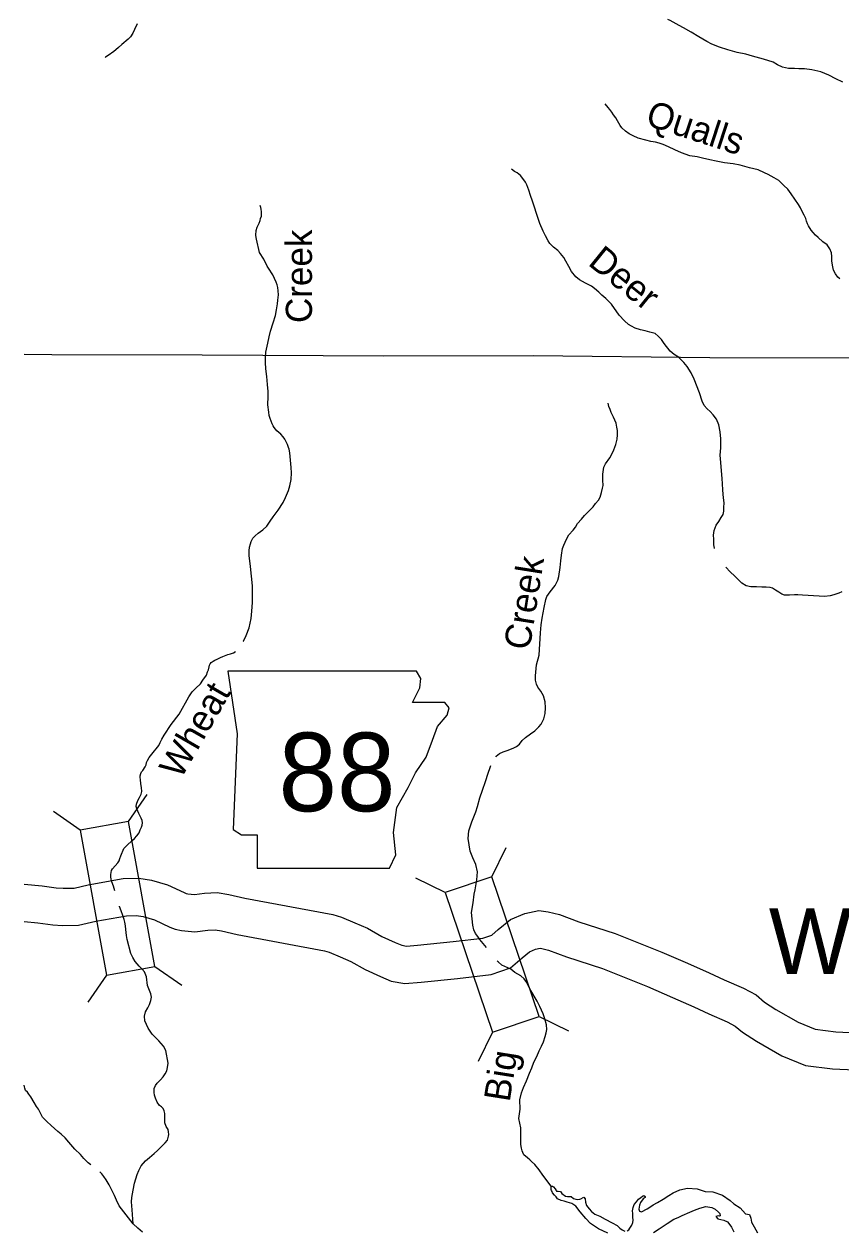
# Model space of a CAD drawing. Extents: x -492261 to -432772, y 1441225 to 1452922.
# Drawn here: x -461914.6 to -461749.9, y 1452450.6 to 1452693.5 of the extents above; entities that cross this region are included whole.
import ezdxf

# ---------------------------------------------------------------- set-up
doc = ezdxf.new("R2010")
doc.units = 0
doc.layers.add('Default', color=7, linetype='Continuous')

msp = doc.modelspace()

# ---------------------------------------------------------------- linework, layer by layer
at = {"layer": 'Default'}
for p, q in [((-461893.49, 1452532.85), (-461889.73, 1452538.27)), ((-461903.23, 1452531.08), (-461908.65, 1452534.84)), ((-461820.3, 1452521.7), (-461817.38, 1452527.62)), ((-461829.68, 1452518.52), (-461835.6, 1452521.43)), ((-461888.19, 1452503.63), (-461882.77, 1452499.87)), ((-461897.93, 1452501.86), (-461901.69, 1452496.44)), ((-461810.75, 1452493.58), (-461804.83, 1452490.66)), ((-461820.13, 1452490.39), (-461823.05, 1452484.47))]:
    msp.add_line(p, q, dxfattribs=at)
for points in [[(-461891.79, 1452693.56), (-461892.3, 1452692.45), (-461892.67, 1452691.72), (-461893.11, 1452690.94), (-461893.55, 1452690.51), (-461894.89, 1452689.39), (-461895.53, 1452688.83), (-461896.1, 1452688.38), (-461896.5, 1452688.02), (-461897.61, 1452687.23), (-461898.13, 1452686.88), (-461898.2, 1452686.8)], [(-461772.69, 1452688.32), (-461774.36, 1452688.88), (-461775.92, 1452689.49), (-461776.97, 1452690), (-461778.58, 1452690.94), (-461780.11, 1452691.89), (-461781.62, 1452692.75), (-461782.52, 1452693.24), (-461783.72, 1452693.91), (-461784.3, 1452694.25), (-461784.83, 1452694.47)], [(-461749.54, 1452681.8), (-461750.94, 1452682.51), (-461752.32, 1452683.25), (-461753.98, 1452683.93), (-461755.8, 1452684.31), (-461757.23, 1452684.5), (-461758.37, 1452684.53), (-461759.27, 1452684.57), (-461760, 1452684.56), (-461760.45, 1452684.58), (-461761.67, 1452684.85), (-461762.7, 1452685.33), (-461763.6, 1452685.87), (-461765.51, 1452686.48), (-461767.73, 1452687.08), (-461769.08, 1452687.49), (-461770.83, 1452687.84), (-461772.69, 1452688.32)], [(-461750.13, 1452642.19), (-461750.55, 1452642.55), (-461751.03, 1452643.22), (-461751.39, 1452643.94), (-461751.57, 1452644.64), (-461751.73, 1452645.76), (-461751.72, 1452646.71), (-461751.82, 1452647.44), (-461752.13, 1452648.26), (-461752.71, 1452649.03), (-461753.54, 1452649.67), (-461754.5, 1452650.51), (-461755.03, 1452651.03), (-461755.54, 1452651.55), (-461755.94, 1452652.02), (-461756.45, 1452652.87), (-461756.68, 1452653.29), (-461756.88, 1452653.81), (-461757.01, 1452654.36), (-461757.32, 1452655.01), (-461757.75, 1452655.76), (-461758.08, 1452656.5), (-461758.46, 1452657.17), (-461759.17, 1452658.24), (-461759.91, 1452659.36), (-461760.64, 1452660.25), (-461761.45, 1452661.02), (-461762.43, 1452662.03), (-461763.34, 1452662.57), (-461764.59, 1452663.21), (-461765.32, 1452663.55), (-461766.62, 1452664.14), (-461768.32, 1452664.57), (-461770.2, 1452665.08), (-461771.62, 1452665.36), (-461773.37, 1452665.61), (-461775.05, 1452665.92), (-461776.35, 1452666.16), (-461777.8, 1452666.54), (-461778.9, 1452666.78), (-461780.4, 1452667.01), (-461782.03, 1452667.57), (-461783.36, 1452668.2), (-461784.66, 1452668.77), (-461785.71, 1452669.28), (-461786.54, 1452669.57), (-461787.31, 1452669.76), (-461788.21, 1452669.9), (-461789.24, 1452670.12), (-461790.77, 1452670.57), (-461791.79, 1452670.99), (-461792.57, 1452671.4), (-461793.35, 1452671.95), (-461794.06, 1452672.61), (-461794.44, 1452673.13), (-461794.67, 1452673.58), (-461794.94, 1452674.06), (-461795.3, 1452674.63), (-461795.73, 1452675.25), (-461796.11, 1452675.79), (-461796.47, 1452676.34), (-461796.82, 1452676.76), (-461797.4, 1452677.48)], [(-461775.37, 1452587.84), (-461775.41, 1452587.92), (-461775.54, 1452588.57), (-461775.55, 1452589.75), (-461775.59, 1452590.58), (-461775.49, 1452591.48), (-461775.06, 1452592.53), (-461774.54, 1452593.27), (-461774.03, 1452594.12), (-461773.68, 1452594.7), (-461773.54, 1452595.38), (-461773.52, 1452596.13), (-461773.48, 1452597.06), (-461773.59, 1452598.06), (-461773.71, 1452599.63), (-461773.77, 1452600.98), (-461773.88, 1452601.91), (-461774.14, 1452605.16), (-461774.23, 1452606.69), (-461774.15, 1452608.16), (-461774.12, 1452609.94), (-461774.28, 1452611.39), (-461774.52, 1452612.76), (-461774.98, 1452613.89), (-461775.66, 1452614.8), (-461776.27, 1452615.45), (-461776.85, 1452615.99), (-461777.45, 1452616.71), (-461777.89, 1452617.58), (-461778.43, 1452619.23), (-461779.48, 1452621.99), (-461780.09, 1452623.26), (-461780.9, 1452624.51), (-461781.59, 1452625.35), (-461782.65, 1452626.41), (-461783.5, 1452626.95), (-461784.33, 1452627.65), (-461785.57, 1452629.16), (-461786.1, 1452629.95), (-461786.76, 1452630.65), (-461787.36, 1452631.17), (-461787.91, 1452631.31), (-461788.46, 1452631.48), (-461789.36, 1452631.72), (-461790.31, 1452631.93), (-461791.37, 1452632.27), (-461792.14, 1452632.69), (-461792.7, 1452633.03), (-461793.55, 1452633.72), (-461794.59, 1452634.91), (-461796.13, 1452637.1), (-461796.76, 1452637.72), (-461797.32, 1452638.24), (-461798.1, 1452638.93), (-461798.7, 1452639.5), (-461799.61, 1452640.24), (-461800.21, 1452640.73), (-461801.37, 1452641.32), (-461802.62, 1452642.03), (-461803.35, 1452642.62), (-461804.23, 1452643.69), (-461804.74, 1452644.71), (-461805.38, 1452645.75), (-461805.79, 1452646.52), (-461806.44, 1452647.34), (-461807, 1452647.91), (-461807.88, 1452648.6), (-461808.56, 1452649.3), (-461808.94, 1452649.89), (-461809.47, 1452650.86), (-461809.96, 1452651.83), (-461810.57, 1452653.38), (-461811.27, 1452655.35), (-461811.71, 1452656.67), (-461812.09, 1452657.84), (-461812.48, 1452658.99), (-461812.84, 1452660.09), (-461813.25, 1452661.16), (-461813.5, 1452661.68), (-461813.81, 1452662.15), (-461814.47, 1452663), (-461815.15, 1452663.56), (-461815.72, 1452663.86), (-461816.33, 1452664.28)], [(-461866.45, 1452591.6), (-461865.66, 1452592.38), (-461864.99, 1452593.37), (-461864.33, 1452594.27), (-461863.37, 1452595.61), (-461862.36, 1452597.1), (-461861.9, 1452598.13), (-461861.29, 1452599.54), (-461860.98, 1452600.49), (-461860.74, 1452601.77), (-461860.68, 1452603.13), (-461860.74, 1452604.2), (-461860.88, 1452605.63), (-461861.02, 1452607.13), (-461861.13, 1452607.9), (-461861.23, 1452608.2), (-461861.46, 1452608.82), (-461861.72, 1452609.37), (-461862, 1452609.89), (-461862.33, 1452610.39), (-461862.81, 1452610.89), (-461863.61, 1452611.58), (-461864.17, 1452612.22), (-461864.34, 1452612.57), (-461864.55, 1452612.99), (-461864.96, 1452614.07), (-461865.14, 1452614.69), (-461865.25, 1452615.31), (-461865.41, 1452616.84), (-461865.33, 1452618.47), (-461865.39, 1452619.52), (-461865.48, 1452620.94), (-461865.65, 1452622.49), (-461865.81, 1452624.04), (-461865.88, 1452625.32), (-461865.89, 1452626.39), (-461865.82, 1452627.4), (-461865.68, 1452628.02), (-461865.42, 1452629.23), (-461865.16, 1452630.53), (-461864.89, 1452631.64), (-461864.36, 1452633.35), (-461863.9, 1452634.83), (-461863.67, 1452635.98), (-461863.5, 1452637.16), (-461863.39, 1452637.91), (-461863.3, 1452638.99), (-461863.36, 1452639.81), (-461863.44, 1452640.44), (-461863.57, 1452640.99), (-461863.75, 1452641.54), (-461864.44, 1452643.01), (-461865.27, 1452644.32), (-461865.53, 1452644.77), (-461866.22, 1452646.14), (-461867.08, 1452647.48), (-461867.73, 1452650.18), (-461867.81, 1452650.53), (-461867.84, 1452651.03), (-461867.77, 1452651.95), (-461867.61, 1452652.58), (-461867.19, 1452653.44), (-461867, 1452653.96), (-461866.88, 1452654.37), (-461866.73, 1452654.84), (-461866.69, 1452655.19), (-461866.69, 1452655.67), (-461866.75, 1452656.22), (-461866.82, 1452656.57), (-461866.95, 1452656.97)], [(-461644.11, 1452625.59), (-461644.17, 1452625.59), (-461679.88, 1452625.65), (-461709.52, 1452625.91), (-461746.15, 1452626.19), (-461776.34, 1452626.27), (-461811.87, 1452626.66), (-461842.06, 1452626.62), (-461878.66, 1452626.85), (-461908.95, 1452626.91), (-461914.56, 1452626.93)], [(-461797.85, 1452600.54), (-461797.88, 1452601.61), (-461797.9, 1452602.86), (-461797.69, 1452604.22), (-461797.37, 1452604.95), (-461796.48, 1452606.16), (-461796.02, 1452607.01), (-461795.7, 1452607.77), (-461795.29, 1452608.8), (-461795.02, 1452609.88), (-461794.93, 1452610.76), (-461794.94, 1452611.66), (-461795.05, 1452612.31), (-461795.23, 1452613.1), (-461795.74, 1452614.35), (-461796.2, 1452615.25), (-461796.43, 1452615.84), (-461796.69, 1452616.49), (-461796.8, 1452617.12)], [(-461799.87, 1452596.26), (-461799.35, 1452596.93), (-461798.75, 1452597.59), (-461798.45, 1452598.22), (-461798.16, 1452599.15), (-461797.96, 1452600.02), (-461797.85, 1452600.54)], [(-461811.5, 1452562.21), (-461811.27, 1452564.44), (-461810.77, 1452566.37), (-461810.46, 1452570.88), (-461810.31, 1452572.51), (-461810.14, 1452573.79), (-461809.74, 1452575.95), (-461809.41, 1452577.6), (-461809.22, 1452578.2), (-461808.53, 1452579.14), (-461807.49, 1452580.43), (-461806.96, 1452581.51), (-461806.74, 1452582.24), (-461806.51, 1452584.02), (-461806.4, 1452585.4), (-461806.26, 1452586.55), (-461806, 1452587.88), (-461805.78, 1452588.56), (-461805.24, 1452589.74), (-461804.78, 1452590.64), (-461803.89, 1452591.53), (-461803.4, 1452592.19), (-461802.98, 1452592.87), (-461802.22, 1452593.8), (-461801.63, 1452594.54), (-461800.47, 1452595.65), (-461799.87, 1452596.26)], [(-461870.4, 1452569.13), (-461870.36, 1452569.2), (-461869.79, 1452570.31), (-461869.21, 1452571.89), (-461868.81, 1452573.75), (-461868.62, 1452575.23), (-461868.52, 1452576.96), (-461868.54, 1452578.96), (-461868.55, 1452580.36), (-461868.94, 1452584.23), (-461869.19, 1452586.46), (-461869.2, 1452587.41), (-461869.11, 1452588.16), (-461868.94, 1452588.77), (-461868.79, 1452589.24), (-461868.48, 1452589.95), (-461867.98, 1452590.43), (-461867.39, 1452590.96), (-461866.45, 1452591.6)], [(-461749.72, 1452579.11), (-461750.36, 1452578.87), (-461751.36, 1452578.51), (-461752.1, 1452578.3), (-461753.22, 1452578.21), (-461754.3, 1452578.23), (-461755.45, 1452578.29), (-461756.52, 1452578.38), (-461757.69, 1452578.46), (-461758.59, 1452578.53), (-461759.24, 1452578.55), (-461760.26, 1452578.48), (-461760.86, 1452578.43), (-461761.31, 1452578.47), (-461761.79, 1452578.64), (-461762.44, 1452579.04), (-461763.09, 1452579.48), (-461763.7, 1452579.85), (-461764.15, 1452579.99), (-461765, 1452580.06), (-461765.84, 1452580.1), (-461766.92, 1452580.11), (-461768.09, 1452580.15), (-461768.99, 1452580.34), (-461769.87, 1452580.85), (-461770.58, 1452581.52), (-461771.31, 1452582.26), (-461772.24, 1452583.13), (-461773.08, 1452584.07)], [(-461896.24, 1452518.89), (-461896.54, 1452519.8), (-461896.87, 1452520.69), (-461897, 1452521.22), (-461897.08, 1452521.67), (-461897.09, 1452522.14), (-461896.95, 1452522.94), (-461896.75, 1452523.3), (-461896.21, 1452523.9), (-461895.67, 1452524.49), (-461895.42, 1452524.89), (-461895.25, 1452525.39), (-461895.06, 1452525.94), (-461894.47, 1452527.4), (-461893.81, 1452528.11), (-461892.82, 1452528.97), (-461892.32, 1452529.4), (-461891.85, 1452529.94), (-461891.36, 1452530.59), (-461891.19, 1452531.14), (-461890.92, 1452531.7), (-461890.75, 1452532.13), (-461890.71, 1452532.58), (-461890.76, 1452533.08), (-461890.94, 1452533.5), (-461891.45, 1452534.47), (-461891.86, 1452535.42), (-461891.97, 1452535.87), (-461891.87, 1452536.32), (-461891.63, 1452537.05), (-461891.29, 1452537.7), (-461890.99, 1452538.33), (-461890.85, 1452538.86), (-461890.88, 1452539.68), (-461891.02, 1452540.43), (-461891.12, 1452541.28), (-461891.15, 1452541.73), (-461891.13, 1452542.06), (-461891.01, 1452542.51), (-461890.87, 1452542.84), (-461890.64, 1452543.14), (-461890.18, 1452543.87), (-461889.98, 1452544.27), (-461889.86, 1452544.73), (-461889.67, 1452545.15), (-461889.37, 1452545.73), (-461888.81, 1452546.44), (-461887.4, 1452548.16), (-461887.11, 1452548.76), (-461886.79, 1452549.42), (-461886.35, 1452550.22), (-461884.93, 1452552.42), (-461883.33, 1452554.49), (-461881.37, 1452557.94), (-461880.7, 1452558.97), (-461879.96, 1452559.71), (-461878.97, 1452560.57), (-461878.51, 1452561.35), (-461877.82, 1452562.36), (-461877.58, 1452562.99), (-461877.38, 1452563.44), (-461877.24, 1452564.02), (-461877.17, 1452564.32), (-461877.05, 1452564.64), (-461876.82, 1452564.87), (-461876.43, 1452565.18), (-461876.08, 1452565.33), (-461875.61, 1452565.56), (-461874.99, 1452565.87), (-461874.47, 1452566.13), (-461873.52, 1452566.49), (-461872.95, 1452566.62), (-461872.38, 1452566.83), (-461871.98, 1452567.06), (-461871.92, 1452567.14)], [(-461819.44, 1452545.89), (-461819.39, 1452545.98), (-461818.74, 1452546.53), (-461817.97, 1452546.87), (-461816.98, 1452547.25), (-461816.51, 1452547.44), (-461815.98, 1452547.64), (-461815.29, 1452547.97), (-461814.72, 1452548.46), (-461814.15, 1452549.16), (-461813.49, 1452549.75), (-461812.45, 1452550.49), (-461811.6, 1452551.1), (-461810.81, 1452551.91), (-461810.32, 1452552.49), (-461809.78, 1452553.52), (-461809.52, 1452554.6), (-461809.43, 1452555.75), (-461809.54, 1452556.93), (-461809.88, 1452558.15), (-461810.42, 1452559.14), (-461811, 1452559.94), (-461811.28, 1452560.49), (-461811.46, 1452561.33), (-461811.5, 1452562.21)], [(-461821.34, 1452507.43), (-461822.01, 1452508.23), (-461822.67, 1452509.05), (-461823.08, 1452509.69), (-461823.56, 1452510.31), (-461823.89, 1452511.03), (-461824.1, 1452511.93), (-461824.26, 1452513.21), (-461824.35, 1452514.48), (-461824.02, 1452516.49), (-461823.86, 1452518.19), (-461823.67, 1452519.1), (-461823.27, 1452521.1), (-461823.16, 1452522.73), (-461823.5, 1452524.18), (-461824.14, 1452525.55), (-461824.63, 1452526.84), (-461825.03, 1452529.42), (-461824.92, 1452530.97), (-461824.31, 1452532.75), (-461823.51, 1452534.82), (-461823.17, 1452535.87), (-461822.67, 1452537.63), (-461822.18, 1452539.14), (-461821.58, 1452540.92), (-461821, 1452542.58), (-461820.64, 1452543.76), (-461820.47, 1452544.14)], [(-461914.56, 1452520.24), (-461910.91, 1452519.87), (-461908.07, 1452519.48), (-461906.67, 1452519.42), (-461904.46, 1452519.44), (-461901.62, 1452520.09), (-461894.6, 1452521.37), (-461891.41, 1452521.4), (-461888.91, 1452521.01), (-461885.66, 1452520.06), (-461882.3, 1452518.51), (-461881.88, 1452518.35), (-461881.54, 1452518.27), (-461880.24, 1452518.14), (-461878.18, 1452518.4), (-461875.63, 1452518.53), (-461873.31, 1452518.17), (-461870.05, 1452517.4), (-461852.34, 1452514.08), (-461850.57, 1452513.6), (-461847.89, 1452512.46), (-461845.32, 1452511.33), (-461842.44, 1452509.69), (-461839.77, 1452508.49), (-461838.4, 1452507.93), (-461837.46, 1452507.75), (-461835.23, 1452507.95), (-461828.04, 1452508.67), (-461822.1, 1452509.37), (-461820.31, 1452509.97), (-461819.02, 1452511.1), (-461816.53, 1452513.13), (-461813.65, 1452514.29), (-461810.79, 1452514.89), (-461808.89, 1452514.63), (-461806.67, 1452514.14), (-461802.72, 1452512.63), (-461795.45, 1452510.29), (-461786, 1452506.51), (-461780.84, 1452504.28), (-461776.47, 1452502.33), (-461773.47, 1452500.94), (-461769.56, 1452499.25), (-461767.01, 1452497.89), (-461765.29, 1452496.46), (-461763.01, 1452494.98), (-461758.5, 1452492.38), (-461755.1, 1452490.99), (-461750.96, 1452490.47), (-461746.77, 1452490.29)], [(-461894.4, 1452513.09), (-461894.68, 1452513.91), (-461895.02, 1452514.86), (-461895.35, 1452515.75), (-461895.36, 1452515.77)], [(-461914.56, 1452512.7), (-461911.8, 1452512.42), (-461908.75, 1452512.01), (-461906.8, 1452511.92), (-461903.57, 1452511.95), (-461900.11, 1452512.75), (-461893.89, 1452513.87), (-461891.95, 1452513.89), (-461890.54, 1452513.67), (-461888.3, 1452513.02), (-461885.18, 1452511.57), (-461884.1, 1452511.17), (-461882.84, 1452510.86), (-461880.14, 1452510.59), (-461877.52, 1452510.92), (-461876.02, 1452511), (-461874.74, 1452510.8), (-461871.6, 1452510.06), (-461854.02, 1452506.77), (-461853.04, 1452506.5), (-461850.88, 1452505.58), (-461848.7, 1452504.62), (-461845.84, 1452503), (-461842.73, 1452501.6), (-461840.55, 1452500.7), (-461837.84, 1452500.18), (-461834.52, 1452500.48), (-461827.23, 1452501.21), (-461820.44, 1452502.01), (-461816.49, 1452503.35), (-461814.18, 1452505.37), (-461812.67, 1452506.6), (-461811.46, 1452507.09), (-461810.52, 1452507.29), (-461810.22, 1452507.25), (-461808.84, 1452506.94), (-461805.21, 1452505.55), (-461797.99, 1452503.23), (-461788.88, 1452499.59), (-461783.85, 1452497.41), (-461779.58, 1452495.51), (-461776.54, 1452494.1), (-461772.81, 1452492.48), (-461771.22, 1452491.63), (-461769.74, 1452490.41), (-461766.93, 1452488.58), (-461761.81, 1452485.63), (-461757.02, 1452483.67), (-461751.58, 1452482.98), (-461747.12, 1452482.8)], [(-461890.67, 1452450.08), (-461891.63, 1452450.87), (-461892.54, 1452451.76), (-461892.77, 1452454.59), (-461892.88, 1452456.21), (-461892.82, 1452457.11), (-461892.56, 1452458.54), (-461892.32, 1452459.97), (-461891.77, 1452461.68), (-461891.43, 1452462.49), (-461890.94, 1452463.49), (-461890.1, 1452464.45), (-461889.26, 1452465.16), (-461888.32, 1452465.97), (-461887.7, 1452466.58), (-461886.86, 1452467.37), (-461886.15, 1452468.08), (-461885.68, 1452468.63), (-461885.56, 1452468.93), (-461885.44, 1452469.41), (-461885.41, 1452469.76), (-461885.44, 1452470.31), (-461885.55, 1452470.76), (-461885.65, 1452470.99), (-461885.93, 1452471.38), (-461886.16, 1452472.13), (-461886.19, 1452472.76), (-461886.16, 1452474.03), (-461886.31, 1452474.53), (-461886.54, 1452474.98), (-461886.89, 1452475.35), (-461887.27, 1452475.65), (-461887.75, 1452476.32), (-461888.09, 1452477.09), (-461888.29, 1452477.71), (-461888.37, 1452478.21), (-461888.31, 1452479.04), (-461888.09, 1452479.64), (-461887.72, 1452480.15), (-461887.08, 1452480.76), (-461886.51, 1452481.39), (-461886.12, 1452481.97), (-461885.8, 1452482.62), (-461885.63, 1452483.3), (-461885.51, 1452484.13), (-461886.01, 1452486.7), (-461886.47, 1452487.57), (-461887.43, 1452488.66), (-461887.99, 1452489.28), (-461888.72, 1452490), (-461889.17, 1452490.62), (-461889.53, 1452491.22), (-461889.91, 1452491.91), (-461890.19, 1452492.71), (-461890.3, 1452493.59), (-461890.11, 1452494.46), (-461889.65, 1452495.27), (-461889.28, 1452496), (-461888.99, 1452496.75), (-461888.9, 1452497.43), (-461888.98, 1452498.13), (-461889.69, 1452499.8), (-461889.89, 1452501.52), (-461890.02, 1452501.87), (-461890.32, 1452502.52), (-461890.8, 1452503.14), (-461891.38, 1452503.68), (-461892.19, 1452504.65), (-461892.65, 1452505.45), (-461893.06, 1452506.24), (-461893.81, 1452509.09), (-461893.92, 1452509.89), (-461893.97, 1452510.46), (-461894.03, 1452511.06), (-461894.14, 1452511.81), (-461894.24, 1452512.56), (-461894.4, 1452513.09)], [(-461808.32, 1452459.34), (-461809.97, 1452461.56), (-461810.73, 1452462.68), (-461811.59, 1452463.74), (-461812.27, 1452464.36), (-461812.63, 1452464.68), (-461813.08, 1452465.08), (-461813.81, 1452465.67), (-461813.88, 1452465.82), (-461814.19, 1452466.47), (-461814.32, 1452467.01), (-461814.43, 1452467.76), (-461814.46, 1452468.36), (-461814.42, 1452469.69), (-461814.46, 1452471.14), (-461814.81, 1452472.99), (-461814.58, 1452474.9), (-461814.65, 1452476.77), (-461814.31, 1452478.15), (-461813.87, 1452479.23), (-461813.29, 1452480.59), (-461812.66, 1452482.1), (-461812.24, 1452483.23), (-461811.81, 1452484.36), (-461811.22, 1452485.5), (-461810.71, 1452486.65), (-461810.29, 1452487.56), (-461809.88, 1452488.44), (-461809.52, 1452489.52), (-461809.3, 1452490.25), (-461809.18, 1452490.95), (-461809.29, 1452491.9), (-461809.58, 1452493.05), (-461809.94, 1452494.1), (-461810.27, 1452494.82), (-461810.6, 1452495.54), (-461810.91, 1452496.26), (-461811.16, 1452496.66), (-461812.61, 1452499.15), (-461813.25, 1452500.39), (-461813.75, 1452501.14), (-461814.41, 1452501.73), (-461815.61, 1452502.44), (-461816.42, 1452503.11), (-461818.27, 1452503.89), (-461819.03, 1452504.56), (-461819.17, 1452504.72)], [(-461901.09, 1452463.67), (-461901.62, 1452464.07), (-461902.51, 1452464.94), (-461903.21, 1452465.71), (-461904.35, 1452466.84), (-461905.56, 1452468.26), (-461906.29, 1452469.1), (-461907.1, 1452469.84), (-461907.75, 1452470.41), (-461909.09, 1452471.57), (-461909.97, 1452472.39), (-461910.83, 1452473.28), (-461911.29, 1452474.2), (-461911.67, 1452474.87), (-461912.05, 1452475.44), (-461912.5, 1452476.21), (-461913.22, 1452477.38), (-461913.57, 1452477.9), (-461913.85, 1452478.28), (-461914.28, 1452478.65), (-461914.41, 1452479.14), (-461914.46, 1452479.37), (-461914.56, 1452479.69)], [(-461892.54, 1452451.76), (-461895.37, 1452455.38), (-461895.93, 1452456.53), (-461896.36, 1452457.47), (-461896.93, 1452458.67), (-461897.44, 1452459.64), (-461898.04, 1452460.66), (-461898.5, 1452461.33), (-461898.88, 1452461.85), (-461899.29, 1452462.28)], [(-461807.67, 1452457.53), (-461808.02, 1452457.99), (-461808.12, 1452458.29), (-461808.22, 1452458.51), (-461808.32, 1452458.66), (-461808.29, 1452458.84), (-461808.32, 1452459.34), (-461808.02, 1452459.34), (-461807.82, 1452459.21), (-461807.52, 1452458.81), (-461807.32, 1452458.49), (-461807.25, 1452458.34), (-461806.92, 1452458.34), (-461806.47, 1452458.26), (-461806.17, 1452457.88), (-461805.42, 1452457.38), (-461805, 1452457.31), (-461804.32, 1452457.26), (-461803.83, 1452456.91), (-461803.33, 1452456.73), (-461802.95, 1452456.68), (-461802.53, 1452456.71), (-461802.33, 1452456.81), (-461801.9, 1452457.11), (-461801.7, 1452457.16), (-461801.45, 1452456.81), (-461801.38, 1452456.16), (-461801.18, 1452455.48), (-461800.63, 1452454.81), (-461800.16, 1452454.25), (-461799.53, 1452453.73), (-461798.48, 1452453.35), (-461797.44, 1452452.7), (-461796.04, 1452451.95), (-461795.01, 1452451.45), (-461794.47, 1452450.92), (-461794.02, 1452450.57), (-461793.44, 1452450.3)], [(-461793.02, 1452450.37), (-461792.64, 1452450.57), (-461792.44, 1452450.87), (-461792.04, 1452451.52), (-461791.84, 1452452.05), (-461791.82, 1452452.53), (-461791.84, 1452453.13), (-461791.89, 1452453.88), (-461791.94, 1452454.38), (-461791.77, 1452455.03), (-461791.62, 1452455.65), (-461791.09, 1452456.23), (-461790.72, 1452456.75), (-461790.24, 1452457.05), (-461789.94, 1452457.33), (-461789.62, 1452457.48), (-461789.37, 1452457.3), (-461789.39, 1452457.1), (-461789.79, 1452456.8), (-461790.32, 1452456.05), (-461790.49, 1452455.55), (-461790.67, 1452454.73), (-461790.54, 1452454.33), (-461790.14, 1452454.18), (-461788.94, 1452454.78), (-461788.05, 1452455.38), (-461787.75, 1452455.58), (-461786.9, 1452456.08), (-461785.75, 1452456.75), (-461784.6, 1452457.45), (-461783.75, 1452458.03), (-461782.35, 1452458.65), (-461780.85, 1452458.98), (-461778.9, 1452458.83), (-461777.28, 1452458.3), (-461775.73, 1452458.23), (-461773.79, 1452457.53), (-461772.24, 1452456.5), (-461771.49, 1452455.82), (-461770.24, 1452454.97), (-461769.14, 1452453.8), (-461768.35, 1452453.67), (-461768.07, 1452452.92), (-461767.92, 1452452.12), (-461767.4, 1452451.14), (-461766.72, 1452449.94)], [(-461796.91, 1452449.9), (-461798.76, 1452450.75), (-461800.38, 1452451.85), (-461801.36, 1452452.83), (-461802.45, 1452454.18), (-461803.33, 1452455.33), (-461804.15, 1452455.86), (-461805.07, 1452456.13), (-461805.72, 1452456.33), (-461806.27, 1452456.46), (-461807.02, 1452456.83), (-461807.32, 1452457.18), (-461807.67, 1452457.53)], [(-461787.67, 1452450.02), (-461786.53, 1452450.75), (-461784.95, 1452451.85), (-461783.58, 1452452.7), (-461782.75, 1452453.05), (-461781.9, 1452453.45), (-461780.36, 1452454.12), (-461779.43, 1452454.5), (-461778.38, 1452454.92), (-461777.11, 1452455.27), (-461775.96, 1452455.05), (-461775.24, 1452454.72), (-461774.59, 1452454.15), (-461774.34, 1452453.85), (-461774.26, 1452453.37), (-461774.36, 1452453.32), (-461774.64, 1452453.37), (-461775.14, 1452453.27), (-461774.74, 1452452.77), (-461773.51, 1452452.5), (-461772.79, 1452452.15), (-461772.49, 1452451.87), (-461771.97, 1452451.09), (-461771.47, 1452450.17)]]:
    msp.add_lwpolyline(points, dxfattribs=at)
for points in [[(-461873.49, 1452563.17), (-461871.59, 1452550.48), (-461872.43, 1452531.23), (-461870.74, 1452530.18), (-461867.57, 1452530.18), (-461867.57, 1452523.41), (-461840.92, 1452523.41), (-461839.65, 1452526.16), (-461840.08, 1452530.6), (-461839.44, 1452535.67), (-461837.12, 1452539.69), (-461835.64, 1452542.65), (-461833.52, 1452545.82), (-461832.25, 1452549.21), (-461831.2, 1452551.96), (-461829.29, 1452554.28), (-461828.87, 1452555.76), (-461829.72, 1452556.82), (-461836.27, 1452556.82), (-461834.79, 1452559.78), (-461834.58, 1452561.69), (-461835.46, 1452563.15)], [(-461903.23, 1452531.08), (-461897.93, 1452501.86), (-461888.19, 1452503.63), (-461893.49, 1452532.85)], [(-461810.75, 1452493.58), (-461820.3, 1452521.7), (-461829.68, 1452518.52), (-461820.13, 1452490.39)]]:
    msp.add_lwpolyline(points, close=True, dxfattribs=at)

# ---------------------------------------------------------------- texts
for s, rotation, p in [('Qualls', 342, (-461789.53, 1452673.26)), ('Creek', 90, (-461856.53, 1452633.29)), ('Deer', 321, (-461801.11, 1452645.15)), ('Creek', 81, (-461812.67, 1452567.22)), ('Wheat', 60, (-461883, 1452541.19)), ('Big', 81, (-461816.69, 1452476.18))]:
    msp.add_text(s, height=5.28, rotation=rotation, dxfattribs=at).set_placement(p)
for s, height, p in [('88', 15.84, (-461863.27, 1452534.91)), ('WASHITA', 13.2, (-461764.43, 1452502.12))]:
    msp.add_text(s, height=height, dxfattribs=at).set_placement(p)

doc.saveas('drawing.dxf')
